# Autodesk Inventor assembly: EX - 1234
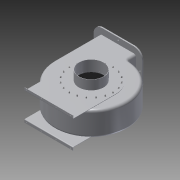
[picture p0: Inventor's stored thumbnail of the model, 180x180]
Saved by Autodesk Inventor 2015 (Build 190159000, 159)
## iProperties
Created: 2006-05
Part Number: EX - 1234
Document SubType Name: Weldment
Designer: ricara
Weld Material: Welded Aluminum-6061
Description: Blower Housing
Mass: 30967 g
Surface Area: 29554.1 cm^2
Volume: 11388.4 cm^3
Density: 2.71918 g/cm^3
Author: ricara
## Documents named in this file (6)
- C:\Users\Public\Documents\Autodesk\Inventor 2015\Samples\Models\Assemblies\Blower\Components\Exhaust.iam
- C:\Users\Public\Documents\Autodesk\Inventor 2015\Samples\Models\Assemblies\Blower\Components\Exhaust.ipt
- C:\Users\Public\Documents\Autodesk\Inventor 2015\Samples\Models\Assemblies\Blower\Components\Exhaust_01.ipt
- C:\Users\Public\Documents\Autodesk\Inventor 2015\Samples\Models\Assemblies\Blower\Components\Exhaust Intake Port.ipt
- C:\Users\Public\Documents\Autodesk\Inventor 2015\Samples\Models\Assemblies\Blower\Components\Exhaust Mount.iam
- C:\Users\Public\Documents\Autodesk\Inventor 2015\Samples\Models\Assemblies\Blower\Exhaust\Design Accelerator\Bolted Connection Motor Mount 21.iam
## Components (24 placed, 5 different names)
1. Exhaust - 001:2 — Mate:1, Mate:2, Angle:1, Mate:4
2. Exhaust_01:3 — Insert:1, Mate:3
3. Exhaust Intake Port:4 — Insert:1
4. Exhaust Mount:5 [sub-assembly] — Mate:1, Mate:2, Angle:1
5. Bolted Connection Exhaust Housing:1 [sub-assembly] — Mate:3, Mate:4
6. Bolted Connection Exhaust Housing:2 [sub-assembly]
7. Bolted Connection Exhaust Housing:3 [sub-assembly]
8. Bolted Connection Exhaust Housing:4 [sub-assembly]
9. Bolted Connection Exhaust Housing:5 [sub-assembly]
10. Bolted Connection Exhaust Housing:6 [sub-assembly]
11. Bolted Connection Exhaust Housing:7 [sub-assembly]
12. Bolted Connection Exhaust Housing:8 [sub-assembly]
13. Bolted Connection Exhaust Housing:9 [sub-assembly]
14. Bolted Connection Exhaust Housing:10 [sub-assembly]
15. Bolted Connection Exhaust Housing:11 [sub-assembly]
16. Bolted Connection Exhaust Housing:12 [sub-assembly]
17. Bolted Connection Exhaust Housing:13 [sub-assembly]
18. Bolted Connection Exhaust Housing:14 [sub-assembly]
19. Bolted Connection Exhaust Housing:15 [sub-assembly]
20. Bolted Connection Exhaust Housing:21 [sub-assembly]
21. Bolted Connection Exhaust Housing:22 [sub-assembly]
22. Bolted Connection Exhaust Housing:23 [sub-assembly]
23. Bolted Connection Exhaust Housing:24 [sub-assembly]
24. Bolted Connection Exhaust Housing:25 [sub-assembly]
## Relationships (6: Mate 4, Insert 1, Angle 1)
- Insert:1: Exhaust_01:3 ↔ Exhaust Intake Port:4
- Mate:1: Exhaust - 001:2 ↔ Exhaust Mount:5
- Mate:2: Exhaust - 001:2 ↔ Exhaust Mount:5
- Angle:1: Exhaust - 001:2 ↔ Exhaust Mount:5
- Mate:3: Exhaust_01:3 ↔ Bolted Connection Exhaust Housing:1
- Mate:4: Exhaust - 001:2 ↔ Bolted Connection Exhaust Housing:1
